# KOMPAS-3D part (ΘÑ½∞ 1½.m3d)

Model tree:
1. Эскиз:1
2. Операция выдавливания:1
     Расстояние 1 = 2
3. Эскиз:2
4. Операция выдавливания:2
     Расстояние 1 = 5
5. Эскиз:3
6. Операция выдавливания:3
     Расстояние 1 = 2
7. Эскиз:4
8. Операция выдавливания:4
     Расстояние 1 = 78
9. Эскиз:5
10. Операция выдавливания:5
     Расстояние 1 = 2
11. Эскиз:6
12. Операция выдавливания:6
     Расстояние 1 = 4.5
13. Эскиз:7
14. Операция выдавливания:7
     Расстояние 1 = 2
15. Скругление:1
     Радиус = 1
16. Скругление:2
     Радиус = 1
17. Эскиз:8
18. Вырезать элемент выдавливания:1
     Расстояние 1 = 10; Угол 1 = 35
19. Эскиз:9
20. Вырезать элемент выдавливания:2
     Расстояние 1 = 10; Угол 1 = 35
21. Эскиз:10
22. Вырезать элемент выдавливания:3
     Расстояние 2 = 22; Расстояние 1 = 22; Угол 1 = 35
23. Эскиз:11
24. Вырезать элемент выдавливания:4
     Расстояние 2 = 2; Расстояние 1 = 2
25. Эскиз:12
26. Вырезать элемент выдавливания:5
     Расстояние 2 = 2; Расстояние 1 = 2; Угол 1 = 35
27. Эскиз:13
28. Вырезать элемент выдавливания:6
     Расстояние 2 = 2; Расстояние 1 = 122
29. Эскиз:14
30. Вырезать элемент выдавливания:8
     Расстояние 2 = 100; Расстояние 1 = 60
31. Эскиз:15
32. Вырезать элемент выдавливания:9
     Расстояние 1 = 10
33. Скругление:3
     Радиус = 2
